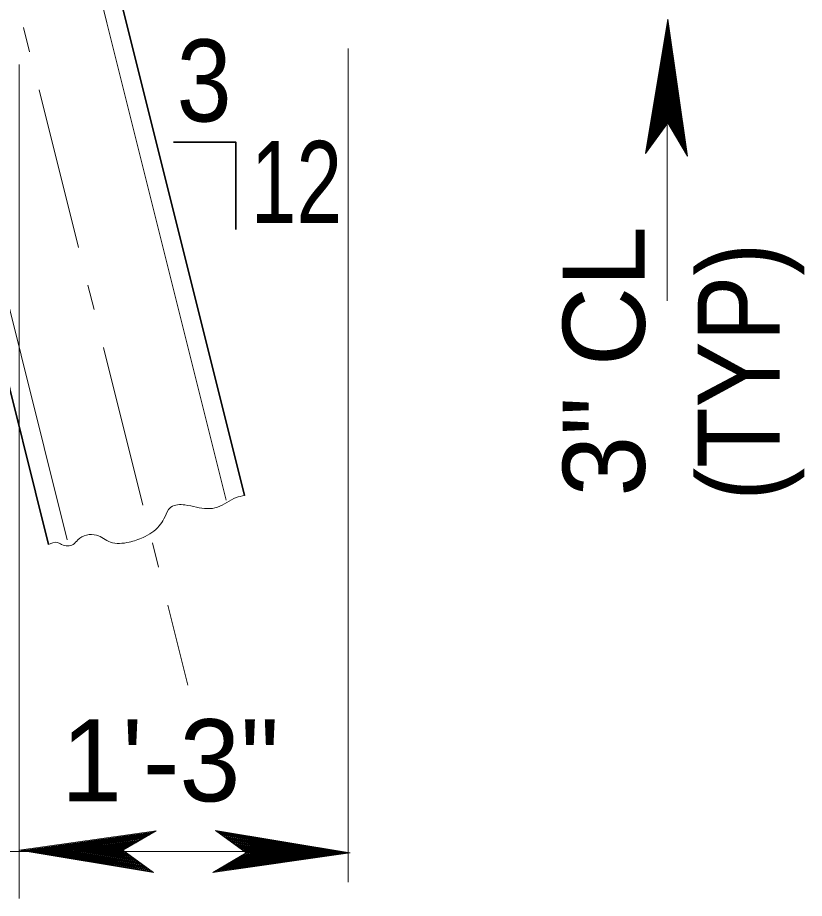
# Model space of a CAD drawing. Extents: x 144 to 252, y 360 to 425.
# Drawn here: x 195.557 to 198.705, y 408.307 to 411.829 of the extents above; entities that cross this region are included whole.
import ezdxf
from ezdxf.enums import TextEntityAlignment as Align

# ---------------------------------------------------------------- set-up
doc = ezdxf.new("R2010")
doc.units = 0
doc.header["$LTSCALE"] = 0.13
doc.linetypes.add('DOT_DASHED', pattern=[7.7, 5, -1.2, 0.3, -1.2])
for name, color, linetype, lineweight in [('16', 7, 'Continuous', 13), ('3', 7, 'Continuous', 13), ('5', 7, 'Continuous', 35)]:
    doc.layers.add(name, color=color, linetype=linetype, lineweight=lineweight)

msp = doc.modelspace()

# ---------------------------------------------------------------- linework, layer by layer
at = {"layer": '16', "lineweight": 35}
msp.add_lwpolyline([(196.1803, 411.3308), (196.4303, 411.3308), (196.4303, 410.9818)], dxfattribs=at)
at = {"layer": '3'}
for p, q in [((198.1586, 411.8236), (198.0693, 411.2859)), ((198.1579, 411.8092), (198.0717, 411.2892)), ((198.1579, 411.7983), (198.074, 411.2924)), ((198.2328, 411.2808), (198.1579, 411.8092)), ((198.2308, 411.2843), (198.1579, 411.7983)), ((198.1586, 411.4082), (198.1586, 411.8236)), ((198.2363, 411.2748), (198.1586, 411.8236)), ((198.1579, 411.7839), (198.0772, 411.2967)), ((198.1579, 411.7712), (198.0798, 411.3004)), ((198.1554, 410.697), (198.1554, 411.7788)), ((198.2282, 411.2889), (198.1579, 411.7839)), ((198.2258, 411.293), (198.1579, 411.7712)), ((198.2258, 411.293), (198.1579, 411.7712)), ((198.1579, 411.7598), (198.0822, 411.3037)), ((198.1579, 411.7454), (198.0854, 411.308)), ((198.1579, 411.7327), (198.0882, 411.3117)), ((198.2236, 411.2967), (198.1579, 411.7598)), ((198.2209, 411.3012), (198.1579, 411.7454)), ((198.2185, 411.3053), (198.1579, 411.7327)), ((196.8798, 408.3713), (196.8798, 411.7053)), ((198.1579, 411.7189), (198.0911, 411.3158)), ((198.1579, 411.7051), (198.0941, 411.3199)), ((198.216, 411.3098), (198.1579, 411.7189)), ((198.2134, 411.3142), (198.1579, 411.7051)), ((198.1579, 411.6918), (198.0969, 411.3238)), ((198.1579, 411.6779), (198.0999, 411.3279)), ((198.1579, 411.6653), (198.1026, 411.3317)), ((198.2109, 411.3184), (198.1579, 411.6918)), ((198.2082, 411.3229), (198.1579, 411.6779)), ((198.206, 411.3269), (198.1579, 411.6653)), ((195.5632, 408.3071), (195.5632, 411.6411)), ((198.1579, 411.6539), (198.1051, 411.3351)), ((198.1579, 411.6382), (198.1084, 411.3397)), ((198.1579, 411.6244), (198.1114, 411.3438)), ((198.2037, 411.3307), (198.1579, 411.6539)), ((198.2009, 411.3357), (198.1579, 411.6382)), ((198.1983, 411.3401), (198.1579, 411.6244)), ((198.1574, 411.6064), (198.1145, 411.348)), ((198.1574, 411.5925), (198.1175, 411.3522)), ((198.1941, 411.3472), (198.1574, 411.6064)), ((198.1915, 411.3517), (198.1574, 411.5925)), ((198.196, 411.3441), (198.159, 411.6048)), ((198.1574, 411.5793), (198.1203, 411.356)), ((198.1579, 411.5702), (198.1231, 411.3597)), ((198.1579, 411.5582), (198.1257, 411.3633)), ((198.189, 411.3559), (198.1574, 411.5793)), ((198.1882, 411.3574), (198.1579, 411.5702)), ((198.1859, 411.3613), (198.1579, 411.5582)), ((198.1579, 411.5444), (198.1287, 411.3674)), ((198.1579, 411.5288), (198.1319, 411.3721)), ((198.1832, 411.3657), (198.1579, 411.5444)), ((198.1804, 411.3707), (198.1579, 411.5288)), ((198.1579, 411.5162), (198.1347, 411.3757)), ((198.1579, 411.5029), (198.1375, 411.3797)), ((198.1579, 411.4909), (198.1402, 411.3832)), ((198.178, 411.3748), (198.1579, 411.5162)), ((198.1755, 411.3791), (198.1579, 411.5029)), ((198.1732, 411.3829), (198.1579, 411.4909)), ((198.1579, 411.4764), (198.1432, 411.3875)), ((198.1579, 411.4626), (198.1462, 411.3917)), ((198.1579, 411.4499), (198.1489, 411.3953)), ((198.1706, 411.3876), (198.1579, 411.4764)), ((198.168, 411.392), (198.1579, 411.4626)), ((198.1657, 411.3961), (198.1579, 411.4499)), ((198.1579, 411.4367), (198.1517, 411.3992)), ((198.1579, 411.4253), (198.1542, 411.4027)), ((198.1579, 411.4151), (198.1564, 411.4057)), ((198.161, 411.404), (198.1579, 411.4253)), ((198.1626, 411.4013), (198.159, 411.4264)), ((198.0693, 411.2859), (198.1584, 411.4084)), ((198.1584, 411.4084), (198.2363, 411.2748)), ((196.1116, 408.5772), (195.5628, 408.4995)), ((196.1056, 408.5737), (195.5772, 408.4988)), ((196.1021, 408.5718), (195.5881, 408.4988)), ((196.0975, 408.5691), (195.6025, 408.4988)), ((196.0934, 408.5667), (195.6153, 408.4988)), ((196.0934, 408.5667), (195.6153, 408.4988)), ((196.0897, 408.5645), (195.6266, 408.4988)), ((196.0852, 408.5618), (195.641, 408.4988)), ((196.0811, 408.5594), (195.6538, 408.4988)), ((195.978, 408.4993), (196.1116, 408.5772)), ((196.8867, 408.489), (196.349, 408.5782)), ((196.349, 408.5782), (196.4715, 408.4892)), ((196.8722, 408.4897), (196.3522, 408.5759)), ((196.8614, 408.4897), (196.3555, 408.5736)), ((196.847, 408.4897), (196.3597, 408.5704)), ((196.8342, 408.4897), (196.3635, 408.5677)), ((196.8229, 408.4897), (196.3668, 408.5653)), ((196.8085, 408.4897), (196.3711, 408.5622)), ((196.7957, 408.4897), (196.3748, 408.5594)), ((196.0767, 408.5569), (195.6675, 408.4988)), ((196.0722, 408.5543), (195.6813, 408.4988)), ((196.068, 408.5518), (195.6946, 408.4988)), ((196.0635, 408.5492), (195.7085, 408.4988)), ((196.0595, 408.5469), (195.7211, 408.4988)), ((196.0557, 408.5447), (195.7325, 408.4988)), ((196.0507, 408.5418), (195.7482, 408.4988)), ((196.0463, 408.5392), (195.762, 408.4988)), ((196.0392, 408.535), (195.78, 408.4983)), ((196.0423, 408.5369), (195.7816, 408.4999)), ((196.0348, 408.5324), (195.7939, 408.4983)), ((196.0305, 408.5299), (195.8071, 408.4983)), ((196.029, 408.5291), (195.8162, 408.4988)), ((196.0251, 408.5268), (195.8282, 408.4988)), ((196.0207, 408.5242), (195.842, 408.4988)), ((196.782, 408.4897), (196.3789, 408.5565)), ((196.7682, 408.4897), (196.383, 408.5535)), ((196.7549, 408.4897), (196.3869, 408.5507)), ((196.741, 408.4897), (196.391, 408.5477)), ((196.7284, 408.4897), (196.3947, 408.545)), ((196.717, 408.4897), (196.3982, 408.5425)), ((196.7013, 408.4897), (196.4027, 408.5392)), ((196.6875, 408.4897), (196.4068, 408.5362)), ((196.6695, 408.4902), (196.4111, 408.5331)), ((196.6556, 408.4902), (196.4152, 408.5301)), ((196.6424, 408.4902), (196.4191, 408.5272)), ((196.6333, 408.4897), (196.4228, 408.5245)), ((196.8157, 408.4941), (190.833, 408.4941)), ((195.5628, 408.4995), (196.1005, 408.4102)), ((195.9783, 408.4995), (195.5628, 408.4995)), ((195.5772, 408.4988), (196.0973, 408.4126)), ((195.5881, 408.4988), (196.094, 408.4149)), ((195.6025, 408.4988), (196.0897, 408.4181)), ((195.6153, 408.4988), (196.086, 408.4207)), ((195.6266, 408.4988), (196.0827, 408.4232)), ((195.641, 408.4988), (196.0784, 408.4263)), ((195.6538, 408.4988), (196.0747, 408.4291)), ((195.6675, 408.4988), (196.0706, 408.432)), ((195.6813, 408.4988), (196.0665, 408.435)), ((195.6946, 408.4988), (196.0626, 408.4378)), ((195.7085, 408.4988), (196.0585, 408.4408)), ((195.7211, 408.4988), (196.0547, 408.4435)), ((195.7325, 408.4988), (196.0513, 408.446)), ((195.7482, 408.4988), (196.0468, 408.4493)), ((195.762, 408.4988), (196.0427, 408.4523)), ((195.78, 408.4983), (196.0384, 408.4554)), ((195.7939, 408.4983), (196.0342, 408.4584)), ((195.8071, 408.4983), (196.0304, 408.4613)), ((195.8162, 408.4988), (196.0267, 408.464)), ((195.8282, 408.4988), (196.0231, 408.4666)), ((195.842, 408.4988), (196.019, 408.4696)), ((196.0157, 408.5213), (195.8577, 408.4988)), ((195.8577, 408.4988), (196.0143, 408.4728)), ((196.0116, 408.5189), (195.8702, 408.4988)), ((195.8702, 408.4988), (196.0107, 408.4756)), ((196.0073, 408.5164), (195.8835, 408.4988)), ((195.8835, 408.4988), (196.0067, 408.4784)), ((196.0035, 408.5142), (195.8955, 408.4988)), ((195.8955, 408.4988), (196.0032, 408.4811)), ((195.9988, 408.5115), (195.91, 408.4988)), ((195.91, 408.4988), (195.9989, 408.4841)), ((195.9944, 408.5089), (195.9238, 408.4988)), ((195.9238, 408.4988), (195.9947, 408.4871)), ((195.9903, 408.5066), (195.9365, 408.4988)), ((195.9365, 408.4988), (195.9911, 408.4898)), ((195.9497, 408.4988), (195.9872, 408.4927)), ((195.9851, 408.5035), (195.96, 408.4999)), ((195.9824, 408.5019), (195.9612, 408.4988)), ((195.9612, 408.4988), (195.9837, 408.4951)), ((195.9713, 408.4988), (195.9808, 408.4973)), ((196.1005, 408.4102), (195.978, 408.4993)), ((196.4715, 408.4892), (196.3379, 408.4112)), ((196.3379, 408.4112), (196.8867, 408.489)), ((196.3439, 408.4147), (196.8722, 408.4897)), ((196.3474, 408.4167), (196.8614, 408.4897)), ((196.352, 408.4194), (196.847, 408.4897)), ((196.3561, 408.4218), (196.8342, 408.4897)), ((196.3561, 408.4218), (196.8342, 408.4897)), ((196.3597, 408.424), (196.8229, 408.4897)), ((196.3643, 408.4267), (196.8085, 408.4897)), ((196.3684, 408.4291), (196.7957, 408.4897)), ((196.3728, 408.4316), (196.782, 408.4897)), ((196.3773, 408.4342), (196.7682, 408.4897)), ((196.3815, 408.4367), (196.7549, 408.4897)), ((196.386, 408.4393), (196.741, 408.4897)), ((196.39, 408.4416), (196.7284, 408.4897)), ((196.3937, 408.4438), (196.717, 408.4897)), ((196.3988, 408.4467), (196.7013, 408.4897)), ((196.4032, 408.4493), (196.6875, 408.4897)), ((196.4072, 408.4516), (196.6679, 408.4886)), ((196.4103, 408.4535), (196.6695, 408.4902)), ((196.4147, 408.4561), (196.6556, 408.4902)), ((196.419, 408.4586), (196.6424, 408.4902)), ((196.4205, 408.4594), (196.6333, 408.4897)), ((196.4244, 408.4617), (196.6213, 408.4897)), ((196.6213, 408.4897), (196.4264, 408.5219)), ((196.4288, 408.4643), (196.6075, 408.4897)), ((196.6075, 408.4897), (196.4305, 408.5189)), ((196.4338, 408.4672), (196.5918, 408.4897)), ((196.5918, 408.4897), (196.4352, 408.5157)), ((196.4379, 408.4696), (196.5793, 408.4897)), ((196.5793, 408.4897), (196.4388, 408.5129)), ((196.4422, 408.4721), (196.566, 408.4897)), ((196.566, 408.4897), (196.4427, 408.5101)), ((196.446, 408.4743), (196.554, 408.4897)), ((196.554, 408.4897), (196.4463, 408.5074)), ((196.5395, 408.4897), (196.4506, 408.5044)), ((196.4507, 408.477), (196.5395, 408.4897)), ((196.5257, 408.4897), (196.4547, 408.5014)), ((196.4551, 408.4796), (196.5257, 408.4897)), ((196.513, 408.4897), (196.4584, 408.4987)), ((196.4592, 408.4819), (196.513, 408.4897)), ((196.4998, 408.4897), (196.4623, 408.4958)), ((196.4644, 408.485), (196.4895, 408.4886)), ((196.4883, 408.4897), (196.4657, 408.4934)), ((196.4671, 408.4866), (196.4883, 408.4897)), ((196.4782, 408.4897), (196.4688, 408.4912)), ((196.4712, 408.489), (196.8867, 408.489))]:
    msp.add_line(p, q, dxfattribs=at)
at = {"layer": '5', "linetype": 'DOT_DASHED', "lineweight": 13}
msp.add_line((195.1278, 413.6012), (196.238, 409.1598), dxfattribs=at)
at = {"layer": '5', "lineweight": 13}
for p, q in [((195.2205, 411.8798), (195.7552, 409.7408)), ((195.8918, 411.8952), (195.9133, 411.8089)), ((195.8977, 411.872), (196.3907, 409.8997))]:
    msp.add_line(p, q, dxfattribs=at)
at = {"layer": '5'}
for p, q in [((195.9742, 411.8816), (196.465, 409.9183)), ((195.1458, 411.8627), (195.6808, 409.7222))]:
    msp.add_line(p, q, dxfattribs=at)
at = {"layer": '5', "lineweight": 13}
msp.add_spline([(196.465, 409.9183), (196.4311, 409.9097), (196.3565, 409.8712), (196.2727, 409.8712), (196.2262, 409.8805), (196.1703, 409.8712), (196.161, 409.8619), (196.1424, 409.8247), (196.1238, 409.7967), (196.0587, 409.7502), (196.0027, 409.7316), (195.9283, 409.7316), (195.8725, 409.7595), (195.798, 409.7409), (195.7794, 409.7222), (195.7328, 409.7222), (195.7147, 409.7308), (195.6808, 409.7222)], degree=3, dxfattribs=at)

# ---------------------------------------------------------------- texts
at = {"layer": '16', "width": 0.9}
msp.add_text('3', height=0.3281, dxfattribs=at).set_placement((196.303, 411.4139), align=Align.CENTER)
at = {"layer": '16', "width": 0.75}
msp.add_text('12', height=0.3281, dxfattribs=at).set_placement((196.8552, 411.0077), align=Align.RIGHT)
at = {"layer": '16'}
msp.add_text('3" CL', height=0.3281, rotation=90, dxfattribs=at).set_placement((198.066, 410.9959), align=Align.RIGHT)
at = {"layer": '16', "width": 0.9}
msp.add_text('(TYP)', height=0.3281, rotation=90, dxfattribs=at).set_placement((198.6059, 410.9287), align=Align.RIGHT)
at = {"layer": '16'}
msp.add_text('1\'-3"', height=0.3281, dxfattribs=at).set_placement((196.1671, 408.6952), align=Align.CENTER)

doc.saveas('drawing.dxf')
